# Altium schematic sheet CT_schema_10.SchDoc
size 278 x 170 mm
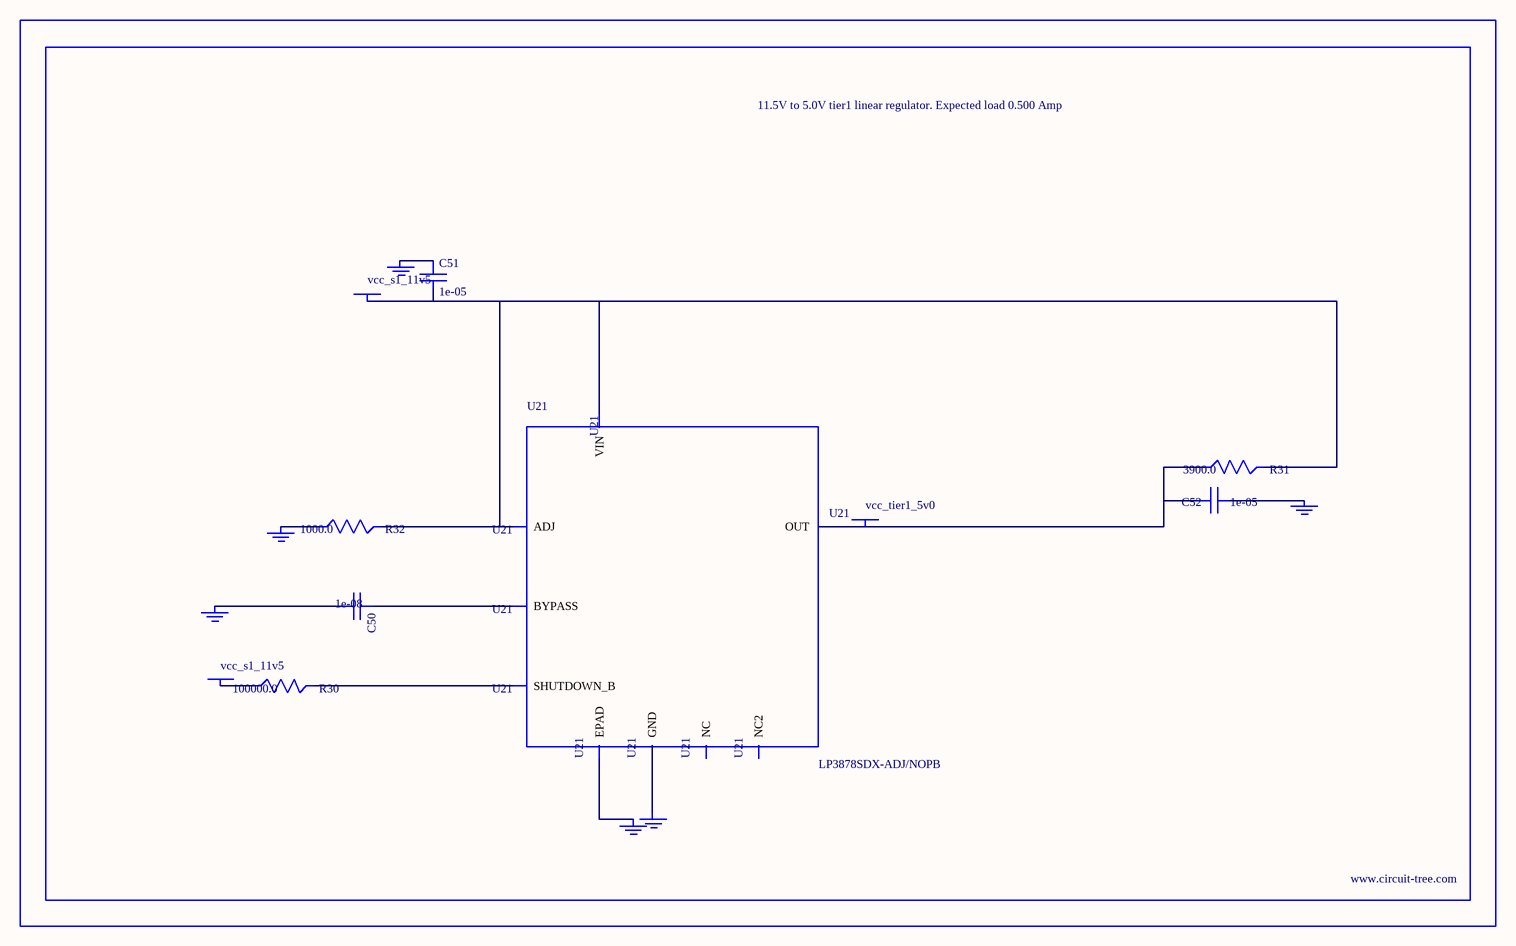
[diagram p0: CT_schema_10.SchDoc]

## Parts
BORDER9  (no value)
C50  1e-08  [C0402]
C51  1e-05  [C1210]
C52  1e-05  [C1210]
GND_INSTANCE_9_0  (no value)
GND_INSTANCE_9_1  (no value)
GND_INSTANCE_9_2  (no value)
GND_INSTANCE_9_3  (no value)
GND_INSTANCE_9_4  (no value)
GND_INSTANCE_9_5  (no value)
POWER_INSTANCE_9_0  vcc_s1_11v5
POWER_INSTANCE_9_1  vcc_s1_11v5
POWER_INSTANCE_9_2  vcc_tier1_5v0
R30  100000.0  [R0603]
R31  3900.0  [R0603]
R32  1000.0  [R0603]
U21  LP3878SDX-ADJ/NOPB  [WSON-8]

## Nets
NetC50_1: C50.1 U21.1(BYPASS)
NetC50_2: C50.2 GND_INSTANCE_9_0.0(GND)
NetC51_1: C51.1 GND_INSTANCE_9_1.0(GND)
NetC51_2: C51.2 POWER_INSTANCE_9_0.0(PWR) R31.2 R32.2 U21.4(VIN) U21.6(ADJ)
NetC52_1: C52.1 GND_INSTANCE_9_2.0(GND)
NetC52_2: C52.2 POWER_INSTANCE_9_2.0(PWR) R31.1 U21.5(OUT)
NetGND_INSTANCE_9_3_0: GND_INSTANCE_9_3.0(GND) R32.1
NetGND_INSTANCE_9_4_0: GND_INSTANCE_9_4.0(GND) U21.PAD(EPAD)
NetGND_INSTANCE_9_5_0: GND_INSTANCE_9_5.0(GND) U21.3(GND)
NetPOWER_INSTANCE_9_1_0: POWER_INSTANCE_9_1.0(PWR) R30.1
NetR30_2: R30.2 U21.8(SHUTDOWN_B)

Not connected (* = marked no-connect by the designer): U21 2(NC) 7(NC2)

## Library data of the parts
BORDER9 = BORDER_PAGE9
C50 = C0402C103K3RAC
C51 = C1210C106K5PACTU
C52 = GRM32DR61E106MA12L
GND_INSTANCE_9_0-GND_INSTANCE_9_5 = GND
POWER_INSTANCE_9_0-POWER_INSTANCE_9_2 = PWR
R30 = RC0603JR-07100KL
R31 = RC0603JR-073K9L
R32 = RC0603JR-071KL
